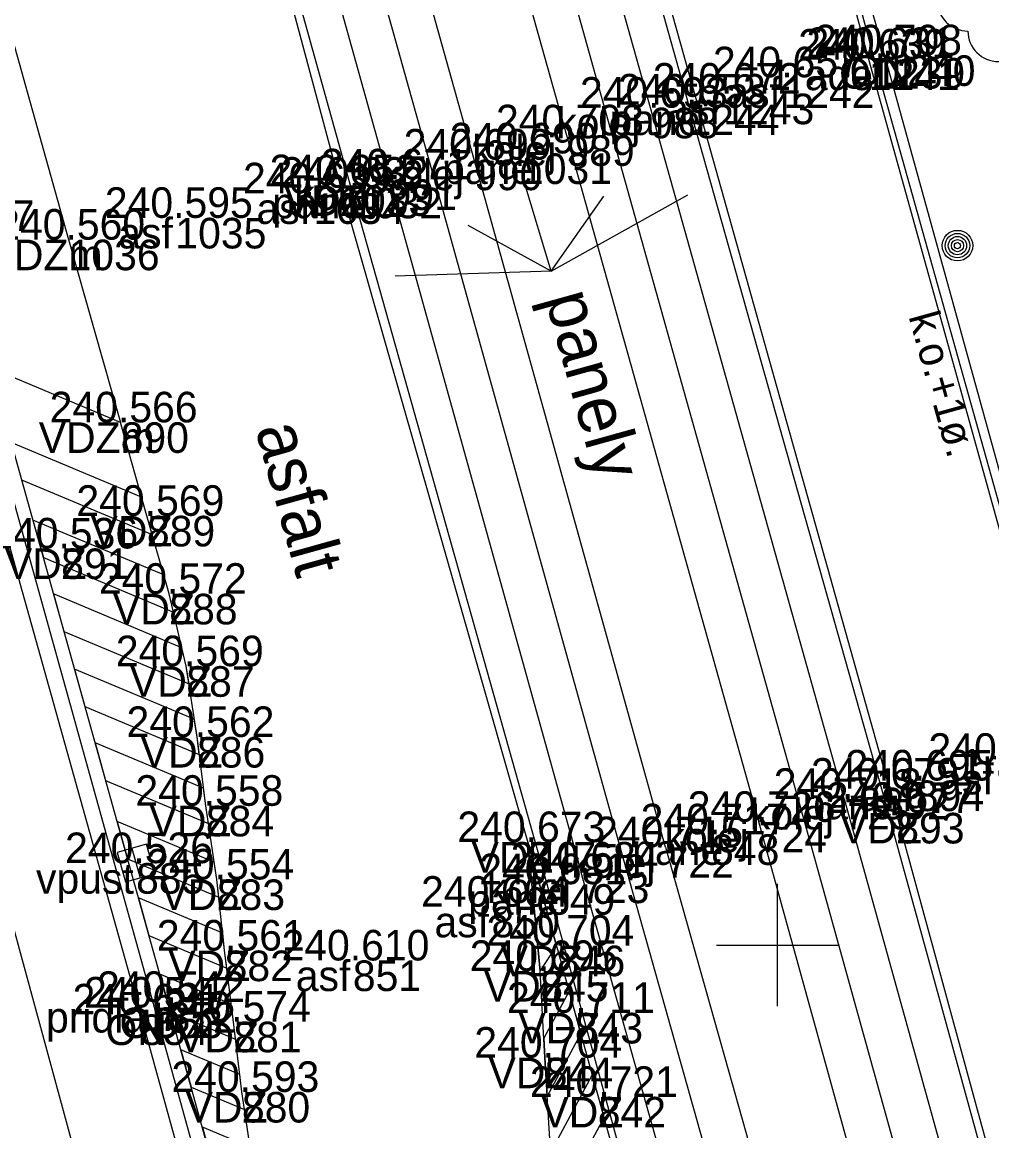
# Model space of a CAD drawing. Extents: x -599098 to -598820, y -1159597 to -1158744.
# Drawn here: x -598962.35 to -598946.5, y -1159153.04 to -1159134.91 of the extents above; entities that cross this region are included whole.
import ezdxf

# ---------------------------------------------------------------- set-up
doc = ezdxf.new("R2010")
doc.units = 0
for name, color, linetype in [('body', 7, 'Continuous'), ('dešťové vpusti šachty', 7, 'Continuous'), ('druh pozemku stromy', 7, 'Continuous'), ('hektometrická síť', 7, 'Continuous'), ('kresba', 7, 'Continuous'), ('kódy bodů', 7, 'Continuous'), ('popisy', 7, 'Continuous'), ('tram_koleje', 7, 'Continuous'), ('tram_osa', 7, 'Continuous'), ('vodorovné dopravní značení_bílé', 7, 'Continuous'), ('vodorovné dopravní značení_modré', 7, 'Continuous'), ('výšky bodů', 7, 'Continuous'), ('značky IS', 7, 'Continuous'), ('čísla bodů', 7, 'Continuous')]:
    doc.layers.add(name, color=color, linetype=linetype)

msp = doc.modelspace()

# ---------------------------------------------------------------- linework, layer by layer
at = {"layer": 'body'}
for p, q in [((-598948.51, -1159135.517), (-598948.51, -1159135.517)), ((-598948.421, -1159135.492), (-598948.421, -1159135.492)), ((-598948.253, -1159135.448), (-598948.253, -1159135.448)), ((-598949.904, -1159135.807), (-598949.904, -1159135.807)), ((-598950.887, -1159136.074), (-598950.887, -1159136.074)), ((-598952.078, -1159136.304), (-598952.078, -1159136.304)), ((-598951.457, -1159136.252), (-598951.457, -1159136.252)), ((-598953.45, -1159136.756), (-598953.45, -1159136.756)), ((-598954.959, -1159137.153), (-598954.959, -1159137.153)), ((-598954.193, -1159137.052), (-598954.193, -1159137.052)), ((-598957.149, -1159137.573), (-598957.149, -1159137.573)), ((-598956.357, -1159137.477), (-598956.357, -1159137.477)), ((-598957.584, -1159137.705), (-598957.584, -1159137.705)), ((-598956.969, -1159137.613), (-598956.969, -1159137.613)), ((-598959.842, -1159138.106), (-598959.842, -1159138.106)), ((-598961.587, -1159138.462), (-598961.587, -1159138.462)), ((-598960.736, -1159141.45), (-598960.736, -1159141.45)), ((-598960.307, -1159142.979), (-598960.307, -1159142.979)), ((-598961.708, -1159143.513), (-598961.708, -1159143.513)), ((-598959.941, -1159144.254), (-598959.941, -1159144.254)), ((-598959.663, -1159145.438), (-598959.663, -1159145.438)), ((-598959.488, -1159146.596), (-598959.488, -1159146.596)), ((-598947.74, -1159147.308), (-598947.74, -1159147.308)), ((-598948.302, -1159147.441), (-598948.302, -1159147.441)), ((-598959.343, -1159147.721), (-598959.343, -1159147.721)), ((-598948.911, -1159147.608), (-598948.911, -1159147.608)), ((-598948.06, -1159147.837), (-598948.06, -1159147.837)), ((-598950.308, -1159147.984), (-598950.308, -1159147.984)), ((-598951.086, -1159148.188), (-598951.086, -1159148.188)), ((-598954.081, -1159148.315), (-598954.081, -1159148.315)), ((-598951.83, -1159148.399), (-598951.83, -1159148.399)), ((-598960.484, -1159148.659), (-598960.484, -1159148.659)), ((-598953.211, -1159148.813), (-598953.211, -1159148.813)), ((-598959.165, -1159148.926), (-598959.165, -1159148.926)), ((-598953.767, -1159149.003), (-598953.767, -1159149.003)), ((-598954.674, -1159149.372), (-598954.674, -1159149.372)), ((-598959.037, -1159150.089), (-598959.037, -1159150.089)), ((-598953.606, -1159150.008), (-598953.606, -1159150.008)), ((-598956.941, -1159150.251), (-598956.941, -1159150.251)), ((-598953.879, -1159150.423), (-598953.879, -1159150.423)), ((-598959.97, -1159150.929), (-598959.97, -1159150.929)), ((-598960.414, -1159151.134), (-598960.414, -1159151.134)), ((-598960.182, -1159151.02), (-598960.182, -1159151.02)), ((-598953.314, -1159151.108), (-598953.314, -1159151.108)), ((-598958.893, -1159151.252), (-598958.893, -1159151.252)), ((-598953.804, -1159151.84), (-598953.804, -1159151.84)), ((-598958.754, -1159152.401), (-598958.754, -1159152.401)), ((-598952.939, -1159152.482), (-598952.939, -1159152.482))]:
    msp.add_line(p, q, dxfattribs=at)
at = {"layer": 'dešťové vpusti šachty'}
msp.add_line((-598960.551, -1159148.418), (-598960.417, -1159148.9), dxfattribs=at)
msp.add_lwpolyline([(-598960.792, -1159148.486), (-598960.657, -1159148.967), (-598960.176, -1159148.832), (-598960.311, -1159148.351)], close=True, dxfattribs=at)
at = {"layer": 'druh pozemku stromy'}
for centre, start, end in [((-598946.89, -1159134.55), 90, 270), ((-598946.39, -1159135.05), 180, 0)]:
    msp.add_arc(centre, 0.5, start, end, dxfattribs=at)
at = {"layer": 'hektometrická síť'}
for p, q in [((-598950, -1159151), (-598950, -1159149)), ((-598951, -1159150), (-598949, -1159150))]:
    msp.add_line(p, q, dxfattribs=at)
at = {"layer": 'kresba'}
for p, q in [((-598953.712, -1159128.146), (-598951.457, -1159136.252)), ((-598956.969, -1159137.613), (-598959.185, -1159129.67)), ((-598948.51, -1159135.517), (-598949.675, -1159131.169)), ((-598948.421, -1159135.492), (-598949.433, -1159131.716)), ((-598949.315, -1159131.673), (-598948.253, -1159135.448)), ((-598945.376, -1159146.794), (-598948.51, -1159135.517)), ((-598945.272, -1159146.749), (-598948.421, -1159135.492)), ((-598948.253, -1159135.448), (-598945.146, -1159146.717)), ((-598951.457, -1159136.252), (-598948.302, -1159147.441)), ((-598953.767, -1159149.003), (-598956.969, -1159137.613)), ((-598964.122, -1159137.906), (-598960.414, -1159151.134)), ((-598960.182, -1159151.02), (-598963.853, -1159137.814)), ((-598959.97, -1159150.929), (-598963.631, -1159137.82)), ((-598963.95, -1159144.36), (-598958.27, -1159165.2)), ((-598948.302, -1159147.441), (-598945.327, -1159158.248)), ((-598950.803, -1159159.842), (-598953.767, -1159149.003)), ((-598957.067, -1159161.364), (-598959.97, -1159150.929)), ((-598960.414, -1159151.134), (-598957.508, -1159161.596)), ((-598957.291, -1159161.484), (-598960.182, -1159151.02))]:
    msp.add_line(p, q, dxfattribs=at)
at = {"layer": 'popisy'}
for q in [(-598954.128, -1159137.547), (-598951.469, -1159137.731), (-598952.842, -1159137.753), (-598955.058, -1159138.228), (-598956.252, -1159139.058)]:
    msp.add_line((-598953.698, -1159138.98), q, dxfattribs=at)
at = {"layer": 'tram_koleje'}
for p, q in [((-598952.078, -1159136.304), (-598954.284, -1159128.404)), ((-598955.669, -1159128.798), (-598953.45, -1159136.756)), ((-598954.959, -1159137.153), (-598957.198, -1159129.11)), ((-598958.588, -1159129.488), (-598956.357, -1159137.477)), ((-598948.911, -1159147.608), (-598952.078, -1159136.304)), ((-598953.45, -1159136.756), (-598950.308, -1159147.984)), ((-598951.83, -1159148.399), (-598954.959, -1159137.153)), ((-598956.357, -1159137.477), (-598953.211, -1159148.813)), ((-598948.911, -1159147.608), (-598945.864, -1159158.602)), ((-598947.268, -1159158.959), (-598950.308, -1159147.984)), ((-598951.83, -1159148.399), (-598948.757, -1159159.313)), ((-598950.145, -1159159.706), (-598953.211, -1159148.813))]:
    msp.add_line(p, q, dxfattribs=at)
at = {"layer": 'tram_osa'}
for points in [[(-598938.102, -1159189.074), (-598940.508, -1159180.437), (-598943.529, -1159169.556), (-598946.566, -1159158.78), (-598949.609, -1159147.796), (-598952.764, -1159136.53), (-598954.976, -1159128.601), (-598958.045, -1159117.58), (-598961.111, -1159106.646), (-598964.189, -1159095.51), (-598967.312, -1159084.422), (-598970.303, -1159073.667), (-598973.399, -1159062.532), (-598976.544, -1159051.232), (-598977.385, -1159048.26), (-598978.019, -1159046.002), (-598979.646, -1159040.156)], [(-598982.522, -1159040.899), (-598980.786, -1159047.126), (-598980.207, -1159049.207), (-598979.432, -1159052.01), (-598976.294, -1159063.274), (-598973.186, -1159074.433), (-598970.188, -1159085.191), (-598967.115, -1159096.22), (-598964.003, -1159107.391), (-598960.951, -1159118.326), (-598957.893, -1159129.299), (-598955.658, -1159137.315), (-598952.52, -1159148.606), (-598949.451, -1159159.509), (-598946.474, -1159170.204), (-598943.386, -1159181.246), (-598941.005, -1159189.804)]]:
    msp.add_lwpolyline(points, dxfattribs=at)
at = {"layer": 'vodorovné dopravní značení_bílé'}
for p, q in [((-598960.393, -1159142.671), (-598962.526, -1159141.778)), ((-598962.354, -1159142.392), (-598960.219, -1159143.286)), ((-598960.03, -1159143.945), (-598962.171, -1159143.048)), ((-598962.171, -1159143.048), (-598961.999, -1159143.662)), ((-598961.999, -1159143.662), (-598959.871, -1159144.554)), ((-598959.734, -1159145.136), (-598961.833, -1159144.257)), ((-598961.833, -1159144.257), (-598961.662, -1159144.871)), ((-598961.662, -1159144.871), (-598959.619, -1159145.727)), ((-598959.532, -1159146.306), (-598961.49, -1159145.485)), ((-598961.49, -1159145.485), (-598961.319, -1159146.099)), ((-598961.319, -1159146.099), (-598959.451, -1159146.882)), ((-598959.38, -1159147.434), (-598961.154, -1159146.691)), ((-598961.154, -1159146.691), (-598960.982, -1159147.305)), ((-598960.982, -1159147.305), (-598959.3, -1159148.009)), ((-598959.207, -1159148.642), (-598960.795, -1159147.977)), ((-598960.795, -1159147.977), (-598960.623, -1159148.59)), ((-598954.081, -1159148.315), (-598948.709, -1159167.741)), ((-598954.081, -1159148.315), (-598953.879, -1159150.423)), ((-598959.068, -1159149.804), (-598960.445, -1159149.227)), ((-598960.445, -1159149.227), (-598960.274, -1159149.841)), ((-598960.274, -1159149.841), (-598959.002, -1159150.374)), ((-598953.879, -1159150.423), (-598953.611, -1159150.015)), ((-598958.929, -1159150.965), (-598960.097, -1159150.476)), ((-598960.097, -1159150.476), (-598959.97, -1159150.929)), ((-598953.407, -1159150.752), (-598953.821, -1159151.524)), ((-598959.97, -1159150.929), (-598959.925, -1159151.09)), ((-598959.925, -1159151.09), (-598958.859, -1159151.537)), ((-598953.765, -1159152.478), (-598953.214, -1159151.45)), ((-598958.789, -1159152.115), (-598959.752, -1159151.711)), ((-598959.752, -1159151.711), (-598959.582, -1159152.324)), ((-598953.029, -1159152.12), (-598953.71, -1159153.389)), ((-598959.582, -1159152.324), (-598958.711, -1159152.689)), ((-598958.62, -1159153.302), (-598959.401, -1159152.975)), ((-598959.401, -1159152.975), (-598959.23, -1159153.589)), ((-598953.652, -1159154.339), (-598952.836, -1159152.818))]:
    msp.add_line(p, q, dxfattribs=at)
for points in [[(-599004.61, -1158945.262), (-599003.444, -1158949.453), (-598994.165, -1158982.574), (-598991.03, -1158993.767), (-598984.936, -1159015.967), (-598978.352, -1159039.475), (-598975.241, -1159050.571), (-598972.159, -1159061.595), (-598965.954, -1159083.858), (-598959.703, -1159106.35), (-598956.549, -1159117.387), (-598953.462, -1159128.573), (-598948.06, -1159147.837), (-598944.998, -1159159.054), (-598943.117, -1159165.778)], [(-598973.022, -1159080.32), (-598971.525, -1159085.618), (-598968.451, -1159096.839), (-598962.368, -1159118.629), (-598959.252, -1159129.728), (-598957.149, -1159137.573), (-598954.079, -1159148.322)], [(-598958.166, -1159157.247), (-598958.431, -1159154.78), (-598958.577, -1159153.592), (-598958.754, -1159152.401), (-598958.893, -1159151.252), (-598959.037, -1159150.089), (-598959.165, -1159148.926), (-598959.343, -1159147.721), (-598959.488, -1159146.596), (-598959.663, -1159145.438), (-598959.941, -1159144.254), (-598960.307, -1159142.979), (-598960.736, -1159141.45)], [(-598960.219, -1159143.286), (-598960.307, -1159142.979), (-598960.393, -1159142.671)], [(-598959.871, -1159144.554), (-598959.941, -1159144.254), (-598960.03, -1159143.945)], [(-598959.619, -1159145.727), (-598959.663, -1159145.438), (-598959.734, -1159145.136)], [(-598959.451, -1159146.882), (-598959.488, -1159146.596), (-598959.532, -1159146.306)], [(-598959.3, -1159148.009), (-598959.343, -1159147.721), (-598959.38, -1159147.434)], [(-598948.709, -1159167.741), (-598951.795, -1159168.653), (-598953.065, -1159163.906), (-598953.12, -1159163.058), (-598953.804, -1159151.84), (-598953.879, -1159150.423), (-598954.081, -1159148.315)], [(-598953.611, -1159150.015), (-598953.612, -1159150.01), (-598954.081, -1159148.315)], [(-598960.623, -1159148.59), (-598960.48, -1159148.65), (-598959.133, -1159149.215)], [(-598959.133, -1159149.215), (-598959.165, -1159148.926), (-598959.207, -1159148.642)], [(-598959.002, -1159150.374), (-598959.037, -1159150.089), (-598959.068, -1159149.804)], [(-598953.214, -1159151.45), (-598953.309, -1159151.107), (-598953.407, -1159150.752)], [(-598958.859, -1159151.537), (-598958.893, -1159151.252), (-598958.929, -1159150.965)], [(-598953.821, -1159151.524), (-598953.804, -1159151.84), (-598953.765, -1159152.478)], [(-598958.711, -1159152.689), (-598958.754, -1159152.401), (-598958.789, -1159152.115)], [(-598952.836, -1159152.818), (-598952.929, -1159152.479), (-598953.029, -1159152.12)]]:
    msp.add_lwpolyline(points, dxfattribs=at)
at = {"layer": 'vodorovné dopravní značení_modré'}
msp.add_lwpolyline([(-598974.717, -1159097.673), (-598973.301, -1159096.019), (-598972.813, -1159097.76), (-598969.71, -1159109.09), (-598966.789, -1159119.67), (-598963.616, -1159131.223), (-598961.587, -1159138.462), (-598960.736, -1159141.45), (-598962.866, -1159140.558)], dxfattribs=at)
at = {"layer": 'značky IS'}
for radius in [0.25, 0.2, 0.15, 0.1, 0.05]:
    msp.add_circle((-598947.06, -1159138.56), radius, dxfattribs=at)

# ---------------------------------------------------------------- texts
at = {"layer": 'kódy bodů'}
for s, p in [('1rade', (-598950.15, -1159136.017)), ('OD', (-598948.993, -1159135.992)), ('ON', (-598948.823, -1159135.948)), ('asf', (-598950.837, -1159136.307)), ('asf', (-598951.82, -1159136.574)), ('kolej', (-598953.618, -1159136.804)), ('pane', (-598952.747, -1159136.752)), ('kolej', (-598954.99, -1159137.256)), ('kolej', (-598956.499, -1159137.653)), ('pane', (-598955.483, -1159137.552)), ('VDZ', (-598958.069, -1159138.073)), ('kolej', (-598957.897, -1159137.977)), ('asf', (-598958.517, -1159138.205)), ('pane', (-598958.259, -1159138.113)), ('asf', (-598960.775, -1159138.606)), ('VDZm', (-598962.926, -1159138.962)), ('VDZm', (-598962.075, -1159141.95)), ('VDZ', (-598961.227, -1159143.479)), ('VDZ', (-598962.628, -1159144.013)), ('VDZ', (-598960.861, -1159144.754)), ('VDZ', (-598960.583, -1159145.938)), ('VDZ', (-598960.408, -1159147.096)), ('1rade', (-598947.016, -1159147.294)), ('asf', (-598947.359, -1159147.535)), ('asf', (-598948.673, -1159147.808)), ('pane', (-598949.592, -1159147.941)), ('VDZ', (-598960.263, -1159148.221)), ('kolej', (-598950.451, -1159148.108)), ('VDZ', (-598948.98, -1159148.337)), ('kolej', (-598951.848, -1159148.484)), ('VDZ', (-598955.001, -1159148.815)), ('kolej', (-598953.37, -1159148.899)), ('pane', (-598952.376, -1159148.688)), ('vpust', (-598962.119, -1159149.159)), ('kolej', (-598954.751, -1159149.313)), ('VDZ', (-598960.085, -1159149.426)), ('pane', (-598955.057, -1159149.503)), ('asf', (-598955.607, -1159149.872)), ('VDZ', (-598959.957, -1159150.589)), ('VDZ', (-598954.526, -1159150.508)), ('asf', (-598957.874, -1159150.751)), ('VDZ', (-598954.799, -1159150.923)), ('pridla', (-598961.956, -1159151.429)), ('ON', (-598960.984, -1159151.634)), ('OD', (-598960.754, -1159151.52)), ('VDZ', (-598954.234, -1159151.608)), ('VDZ', (-598959.813, -1159151.752)), ('VDZ', (-598954.724, -1159152.34)), ('VDZ', (-598959.674, -1159152.901)), ('VDZ', (-598953.859, -1159152.982))]:
    msp.add_text(s, height=0.5, dxfattribs=at).set_placement(p)
at = {"layer": 'popisy'}
for s, height, rotation, p in [('panely', 0.8, 285.5422, (-598953.805, -1159139.412)), ('k.o.+1ø.', 0.5, 285.5312, (-598947.862, -1159139.715)), ('asfalt', 0.8, 285.5601, (-598958.538, -1159141.558))]:
    msp.add_text(s, height=height, rotation=rotation, dxfattribs=at).set_placement(p)
at = {"layer": 'výšky bodů'}
for s, p in [('240.639', (-598949.662, -1159135.517)), ('240.631', (-598949.529, -1159135.492)), ('240.708', (-598949.405, -1159135.448)), ('240.657', (-598951.056, -1159135.807)), ('240.672', (-598952.039, -1159136.074)), ('240.653', (-598952.609, -1159136.252)), ('240.693', (-598953.23, -1159136.304)), ('240.708', (-598954.602, -1159136.756)), ('240.699', (-598956.111, -1159137.153)), ('240.690', (-598955.359, -1159137.052)), ('240.671', (-598957.465, -1159137.477)), ('240.639', (-598958.736, -1159137.705)), ('240.652', (-598958.301, -1159137.573)), ('240.632', (-598958.121, -1159137.613)), ('240.595', (-598960.994, -1159138.106)), ('240.560', (-598962.753, -1159138.462)), ('240.566', (-598961.896, -1159141.45)), ('240.569', (-598961.459, -1159142.979)), ('240.536', (-598962.868, -1159143.513)), ('240.572', (-598961.093, -1159144.254)), ('240.569', (-598960.815, -1159145.438)), ('240.562', (-598960.64, -1159146.596)), ('240.681', (-598947.534, -1159147.035)), ('240.695', (-598948.892, -1159147.308)), ('240.679', (-598949.454, -1159147.441)), ('240.718', (-598950.063, -1159147.608)), ('240.558', (-598960.495, -1159147.721)), ('240.677', (-598949.212, -1159147.837)), ('240.726', (-598951.468, -1159147.984)), ('240.717', (-598952.238, -1159148.188)), ('240.673', (-598955.233, -1159148.315)), ('240.715', (-598952.982, -1159148.399)), ('240.526', (-598961.644, -1159148.659)), ('240.554', (-598960.317, -1159148.926)), ('240.684', (-598954.363, -1159148.813)), ('240.681', (-598954.875, -1159149.003)), ('240.664', (-598955.826, -1159149.372)), ('240.704', (-598954.758, -1159150.008)), ('240.561', (-598960.145, -1159150.089)), ('240.610', (-598958.107, -1159150.251)), ('240.695', (-598955.031, -1159150.423)), ('240.542', (-598961.122, -1159150.929)), ('240.681', (-598961.522, -1159151.134)), ('240.547', (-598961.334, -1159151.02)), ('240.711', (-598954.422, -1159151.108)), ('240.574', (-598960.045, -1159151.252)), ('240.704', (-598954.956, -1159151.84)), ('240.593', (-598959.906, -1159152.401)), ('240.721', (-598954.047, -1159152.482))]:
    msp.add_text(s, height=0.5, dxfattribs=at).set_placement(p)
at = {"layer": 'čísla bodů'}
for s, p in [('1241', (-598948.51, -1159136.017)), ('1239', (-598948.421, -1159135.992)), ('1240', (-598948.253, -1159135.948)), ('1242', (-598949.904, -1159136.307)), ('1243', (-598950.887, -1159136.574)), ('988', (-598952.078, -1159136.804)), ('1244', (-598951.457, -1159136.752)), ('989', (-598953.45, -1159137.256)), ('990', (-598954.959, -1159137.653)), ('1031', (-598954.193, -1159137.552)), ('1033', (-598957.149, -1159138.073)), ('991', (-598956.357, -1159137.977)), ('1034', (-598957.584, -1159138.205)), ('1032', (-598956.969, -1159138.113)), ('1037', (-598963.631, -1159138.32)), ('1035', (-598959.842, -1159138.606)), ('1036', (-598961.587, -1159138.962)), ('890', (-598960.736, -1159141.95)), ('889', (-598960.307, -1159143.479)), ('891', (-598961.708, -1159144.013)), ('888', (-598959.941, -1159144.754)), ('887', (-598959.663, -1159145.938)), ('886', (-598959.488, -1159147.096)), ('894', (-598947.74, -1159147.808)), ('892', (-598948.302, -1159147.941)), ('884', (-598959.343, -1159148.221)), ('725', (-598948.911, -1159148.108)), ('893', (-598948.06, -1159148.337)), ('724', (-598950.308, -1159148.484)), ('848', (-598951.086, -1159148.688)), ('847', (-598954.081, -1159148.815)), ('722', (-598951.83, -1159148.899)), ('885', (-598960.484, -1159149.159)), ('723', (-598953.211, -1159149.313)), ('883', (-598959.165, -1159149.426)), ('849', (-598953.767, -1159149.503)), ('850', (-598954.674, -1159149.872)), ('882', (-598959.037, -1159150.589)), ('846', (-598953.606, -1159150.508)), ('851', (-598956.941, -1159150.751)), ('845', (-598953.879, -1159150.923)), ('852', (-598959.97, -1159151.429)), ('854', (-598960.414, -1159151.634)), ('853', (-598960.182, -1159151.52)), ('843', (-598953.314, -1159151.608)), ('881', (-598958.893, -1159151.752)), ('844', (-598953.804, -1159152.34)), ('880', (-598958.754, -1159152.901)), ('842', (-598952.939, -1159152.982))]:
    msp.add_text(s, height=0.5, dxfattribs=at).set_placement(p)

doc.saveas('drawing.dxf')
